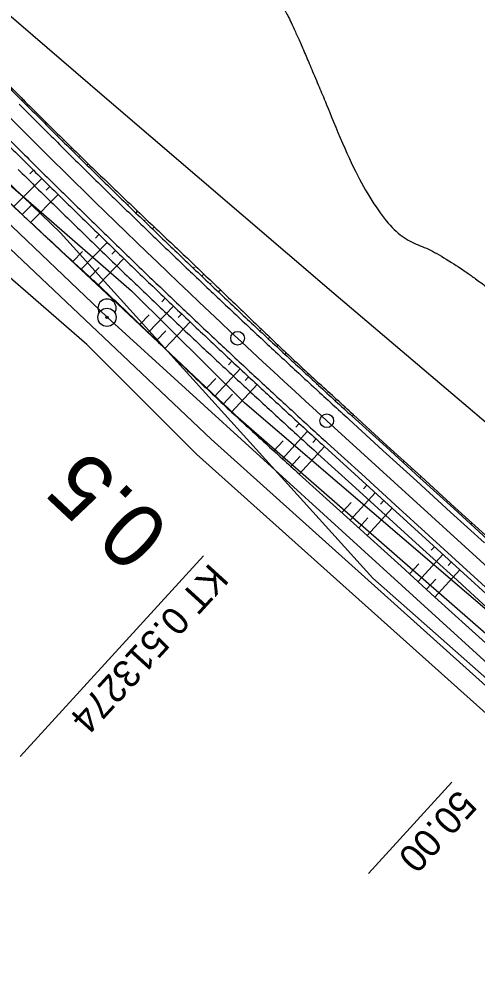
# Model space of a CAD drawing. Extents: x -495905 to -478420, y -1113297 to -1107716.
# Drawn here: x -481388.3 to -481338.3, y -1113006.1 to -1112902.5 of the extents above; entities that cross this region are included whole.
import ezdxf

# ---------------------------------------------------------------- set-up
doc = ezdxf.new("R2010")
doc.units = 0
for name, color, linetype in [('01_OBVOD PÚ', 7, 'Continuous'), ('07_VODOVOD', 7, 'Continuous'), ('2D_VRSTEVNICE', 7, 'Continuous'), ('C11_HATCH_SLOPE_L', 7, 'Continuous'), ('C11_HATCH_SLOPE_R', 7, 'Continuous'), ('C11_HECTOMETRY', 7, 'Continuous'), ('C11_HLBODY', 7, 'Continuous'), ('C11_HRANA_TELESO', 7, 'Continuous'), ('C11_KORUNA', 7, 'Continuous'), ('C11_OSA', 7, 'Continuous'), ('C11_PRIKOP', 7, 'Continuous'), ('C11_STANICENI', 7, 'Continuous'), ('C11_VOZOVKA', 7, 'Continuous'), ('C11_ZPEVKRAJ', 7, 'Continuous'), ('ODVODNĚNÍ PLOŠNÉ', 7, 'Continuous'), ('zamereni', 7, 'Continuous')]:
    doc.layers.add(name, color=color, linetype=linetype)

msp = doc.modelspace()

# ---------------------------------------------------------------- linework, layer by layer
at = {"layer": '01_OBVOD PÚ'}
for p, q in [((-481426.67, -1112889.24), (-481378.69, -1112935.08)), ((-481378.69, -1112935.08), (-481286.24, -1113019.27))]:
    msp.add_line(p, q, dxfattribs=at)
at = {"layer": '07_VODOVOD'}
msp.add_lwpolyline([(-481447.47, -1112865.77), (-481438.82, -1112866.21), (-481429.96, -1112867.07), (-481404.32, -1112889.15), (-481378.96, -1112910.98), (-481353.92, -1112932.45), (-481328.63, -1112953.9), (-481296.87, -1112980.63), (-481265.19, -1113007.37), (-481233.34, -1113034.37), (-481201.77, -1113061.42), (-481169.99, -1113088.44), (-481138.52, -1113115.13), (-481106.63, -1113142.02), (-481094.66, -1113152.18)], dxfattribs=at)
at = {"layer": '2D_VRSTEVNICE'}
msp.add_open_spline([(-481551.3, -1112756.92), (-481547.44, -1112761.88), (-481547.11, -1112762.46), (-481545.92, -1112763.5), (-481537.58, -1112762.56), (-481513.68, -1112779.11), (-481513.68, -1112779.11), (-481513.68, -1112779.11), (-481491.05, -1112801.05), (-481482.63, -1112813.08), (-481477.05, -1112818.52), (-481476.8, -1112818.75), (-481456.22, -1112823.29), (-481442.02, -1112835.86), (-481424.8, -1112850.42), (-481413.21, -1112859.51), (-481391.62, -1112878.03), (-481383.26, -1112885.76), (-481360.32, -1112899.5), (-481357.85, -1112904.16), (-481349.13, -1112925.41), (-481341.11, -1112928.52), (-481329.78, -1112937.87), (-481311.64, -1112957.65), (-481301.83, -1112966.08), (-481283.86, -1112978.01), (-481278.86, -1112980.3), (-481258.37, -1112999.07), (-481255.38, -1113002.96), (-481236.21, -1113021.08), (-481230.44, -1113026.21), (-481206.76, -1113043.85), (-481197.57, -1113052.01), (-481170.89, -1113066.19)], degree=2, dxfattribs=at)
at = {"layer": 'C11_HATCH_SLOPE_L'}
for p, q in [((-481387.96, -1112911.41), (-481387.84, -1112911.3)), ((-481383.54, -1112915.82), (-481383.48, -1112915.75)), ((-481383.42, -1112915.69), (-481383.42, -1112915.69)), ((-481382.66, -1112916.7), (-481382.53, -1112916.56)), ((-481381.77, -1112917.57), (-481381.7, -1112917.5)), ((-481381.63, -1112917.43), (-481381.63, -1112917.43)), ((-481380.88, -1112918.45), (-481380.74, -1112918.3)), ((-481376.43, -1112922.81), (-481376.34, -1112922.72)), ((-481376.25, -1112922.62), (-481376.25, -1112922.62)), ((-481375.53, -1112923.68), (-481375.35, -1112923.49)), ((-481374.64, -1112924.55), (-481374.54, -1112924.45)), ((-481374.44, -1112924.35), (-481374.44, -1112924.35)), ((-481373.74, -1112925.41), (-481373.54, -1112925.21)), ((-481369.24, -1112929.73), (-481369.12, -1112929.61)), ((-481369.01, -1112929.49), (-481369.01, -1112929.49)), ((-481368.34, -1112930.59), (-481368.11, -1112930.35)), ((-481367.43, -1112931.45), (-481367.32, -1112931.33)), ((-481367.21, -1112931.21), (-481367.21, -1112931.21)), ((-481366.53, -1112932.31), (-481366.3, -1112932.07)), ((-481361.98, -1112936.58), (-481361.9, -1112936.49)), ((-481361.81, -1112936.39), (-481361.81, -1112936.39)), ((-481361.07, -1112937.43), (-481360.91, -1112937.26)), ((-481360.16, -1112938.28), (-481360.08, -1112938.2)), ((-481360.01, -1112938.12), (-481360.01, -1112938.12)), ((-481359.24, -1112939.13), (-481359.1, -1112938.98)), ((-481354.66, -1112943.35), (-481354.6, -1112943.28)), ((-481354.53, -1112943.22), (-481354.53, -1112943.22)), ((-481353.74, -1112944.2), (-481353.61, -1112944.06)), ((-481352.82, -1112945.04), (-481352.75, -1112944.97)), ((-481352.69, -1112944.9), (-481352.69, -1112944.9)), ((-481351.89, -1112945.88), (-481351.77, -1112945.74)), ((-481347.28, -1112950.09), (-481347.21, -1112950.02)), ((-481347.15, -1112949.95), (-481347.15, -1112949.95)), ((-481346.35, -1112950.93), (-481346.23, -1112950.79)), ((-481345.43, -1112951.77), (-481345.36, -1112951.71)), ((-481345.3, -1112951.64), (-481345.3, -1112951.64)), ((-481344.5, -1112952.62), (-481344.38, -1112952.48)), ((-481339.89, -1112956.83), (-481339.82, -1112956.76)), ((-481339.76, -1112956.69), (-481339.76, -1112956.69)), ((-481338.96, -1112957.67), (-481338.84, -1112957.53))]:
    msp.add_line(p, q, dxfattribs=at)
at = {"layer": 'C11_HATCH_SLOPE_R'}
for p, q in [((-481386.72, -1112919.01), (-481387.11, -1112919.41)), ((-481385.83, -1112919.89), (-481388.87, -1112922.97)), ((-481384.04, -1112921.65), (-481387.04, -1112924.7)), ((-481384.93, -1112920.77), (-481385.33, -1112921.17)), ((-481386.84, -1112922.7), (-481387.96, -1112923.84)), ((-481378.67, -1112926.91), (-481381.5, -1112929.83)), ((-481379.57, -1112926.04), (-481379.95, -1112926.43)), ((-481381.38, -1112927.9), (-481382.43, -1112928.98)), ((-481377.77, -1112927.78), (-481378.15, -1112928.18)), ((-481376.86, -1112928.65), (-481379.64, -1112931.52)), ((-481379.55, -1112929.62), (-481380.57, -1112930.68)), ((-481372.35, -1112932.99), (-481372.72, -1112933.38)), ((-481371.44, -1112933.85), (-481374.19, -1112936.74)), ((-481374.09, -1112934.82), (-481375.09, -1112935.87)), ((-481370.53, -1112934.71), (-481370.9, -1112935.11)), ((-481369.62, -1112935.57), (-481372.38, -1112938.49)), ((-481372.28, -1112936.56), (-481373.28, -1112937.62)), ((-481365.06, -1112939.87), (-481365.43, -1112940.26)), ((-481364.14, -1112940.72), (-481366.92, -1112943.71)), ((-481366.81, -1112941.75), (-481367.83, -1112942.84)), ((-481362.3, -1112942.43), (-481365.09, -1112945.44)), ((-481363.22, -1112941.57), (-481363.59, -1112941.97)), ((-481364.98, -1112943.47), (-481366.01, -1112944.57)), ((-481356.77, -1112947.52), (-481359.53, -1112950.54)), ((-481357.7, -1112946.67), (-481358.06, -1112947.07)), ((-481359.44, -1112948.58), (-481360.46, -1112949.69)), ((-481355.85, -1112948.36), (-481356.21, -1112948.76)), ((-481354.92, -1112949.2), (-481357.68, -1112952.22)), ((-481357.59, -1112950.27), (-481358.6, -1112951.38)), ((-481350.31, -1112953.42), (-481350.67, -1112953.81)), ((-481349.38, -1112954.26), (-481352.12, -1112957.26)), ((-481352.03, -1112955.31), (-481353.04, -1112956.42)), ((-481348.46, -1112955.1), (-481348.82, -1112955.49)), ((-481347.54, -1112955.94), (-481350.27, -1112958.94)), ((-481350.18, -1112956.99), (-481351.19, -1112958.09)), ((-481342, -1112961), (-481344.71, -1112963.97)), ((-481342.92, -1112960.15), (-481343.27, -1112960.54)), ((-481344.63, -1112962.03), (-481345.64, -1112963.13)), ((-481341.07, -1112961.84), (-481341.42, -1112962.22)), ((-481340.15, -1112962.68), (-481342.86, -1112965.65)), ((-481342.78, -1112963.71), (-481343.78, -1112964.81))]:
    msp.add_line(p, q, dxfattribs=at)
at = {"layer": 'C11_HECTOMETRY'}
msp.add_circle((-481364.43, -1112937.37), 0.75, dxfattribs=at)
at = {"layer": 'C11_HLBODY'}
msp.add_line((-481368.16, -1112961.16), (-481388.18, -1112983.1), dxfattribs=at)
msp.add_circle((-481354.68, -1112946.38), 0.75, dxfattribs=at)
at = {"layer": 'C11_HRANA_TELESO'}
for p, q in [((-481351.77, -1112945.74), (-481348.07, -1112949.11)), ((-481348.07, -1112949.11), (-481344.38, -1112952.48)), ((-481357.68, -1112952.22), (-481353.97, -1112955.58)), ((-481344.38, -1112952.48), (-481340.68, -1112955.85)), ((-481353.97, -1112955.58), (-481350.27, -1112958.94)), ((-481340.68, -1112955.85), (-481336.99, -1112959.22)), ((-481350.27, -1112958.94), (-481346.56, -1112962.29)), ((-481346.56, -1112962.29), (-481342.86, -1112965.65)), ((-481342.86, -1112965.65), (-481339.15, -1112969.01)), ((-481339.15, -1112969.01), (-481335.45, -1112972.37))]:
    msp.add_line(p, q, dxfattribs=at)
for centre, radius, start, end in [((-479258.59, -1110808.22), 2992.76, 224.55002, 224.64563), ((-480681.84, -1112206.5), 997.58, 224.95085, 225.23733), ((-480686.36, -1112202.08), 997.56, 225.6006, 225.88709), ((-480686.39, -1112202.11), 997.52, 225.88699, 226.17348), ((-480697.01, -1112191.86), 1006.58, 226.43672, 226.72327), ((-480686.56, -1112202), 997.48, 226.18489, 226.47138), ((-480699.38, -1112189.79), 1006.46, 226.90239, 227.18897), ((-480687.66, -1112201.01), 997.44, 226.55661, 226.8431), ((-480703, -1112186.65), 1006.32, 227.46194, 227.74856), ((-480679.68, -1112208.61), 997.42, 226.21009, 226.49658), ((-480684.81, -1112203.71), 1006.23, 226.32831, 226.6148), ((-480672.04, -1112215.89), 997.45, 225.89046, 226.17696), ((-480673.73, -1112214.33), 1006.24, 225.74102, 226.02751), ((-480672.18, -1112215.67), 997.51, 226.1914, 226.4779), ((-480674.24, -1112213.77), 1006.29, 226.07011, 226.3566), ((-480677.51, -1112210.59), 997.55, 226.9005, 227.18698), ((-480674.51, -1112213.46), 1006.33, 226.38005, 226.66654), ((-481690.02, -1113312.3), 498.78, 47.3001, 47.8736), ((-480681.85, -1112206.57), 1006.35, 227.23967, 227.52615), ((-481021.06, -1112578.22), 503.17, 227.4401, 228.0118)]:
    msp.add_arc(centre, radius, start, end, dxfattribs=at)
at = {"layer": 'C11_KORUNA'}
for p, q in [((-481351.89, -1112945.88), (-481348.2, -1112949.25)), ((-481354.92, -1112949.2), (-481351.23, -1112952.57)), ((-481348.2, -1112949.25), (-481344.5, -1112952.62)), ((-481351.23, -1112952.57), (-481347.54, -1112955.94)), ((-481344.5, -1112952.62), (-481340.81, -1112955.99)), ((-481347.54, -1112955.94), (-481343.84, -1112959.31)), ((-481340.81, -1112955.99), (-481337.12, -1112959.36)), ((-481343.84, -1112959.31), (-481340.15, -1112962.68)), ((-481340.15, -1112962.68), (-481336.45, -1112966.05))]:
    msp.add_line(p, q, dxfattribs=at)
for centre, radius, start, end in [((-479264.4, -1110801.9), 2993.25, 224.71435, 224.80996), ((-480680.81, -1112207.53), 997.75, 224.8676, 225.15408), ((-480680.81, -1112207.53), 1002.25, 224.8676, 225.15408), ((-480680.81, -1112207.53), 997.75, 225.15408, 225.44056), ((-480680.81, -1112207.53), 1002.25, 225.15408, 225.44056), ((-480680.81, -1112207.53), 997.75, 225.44056, 225.72704), ((-480680.81, -1112207.53), 1002.25, 225.44056, 225.72704), ((-480680.81, -1112207.53), 997.75, 225.72704, 226.01352), ((-480680.81, -1112207.53), 1002.25, 225.72704, 226.01352), ((-480680.81, -1112207.53), 997.75, 226.01352, 226.3), ((-480680.81, -1112207.53), 1002.25, 226.01352, 226.3), ((-480680.81, -1112207.53), 997.75, 226.3, 226.58648), ((-480680.81, -1112207.53), 1002.25, 226.3, 226.58648), ((-480680.81, -1112207.53), 997.75, 226.58648, 226.87296), ((-480680.81, -1112207.53), 1002.25, 226.58648, 226.87296), ((-480680.81, -1112207.53), 997.75, 226.87296, 227.15944), ((-480680.81, -1112207.53), 1002.25, 226.87296, 227.15944), ((-480680.81, -1112207.53), 997.75, 227.15944, 227.44592), ((-480680.81, -1112207.53), 1002.25, 227.15944, 227.44592), ((-481017.17, -1112575.97), 498.88, 227.2854, 227.8588), ((-481018.69, -1112577.63), 501.12, 227.2857, 227.8582)]:
    msp.add_arc(centre, radius, start, end, dxfattribs=at)
at = {"layer": 'C11_OSA'}
msp.add_line((-481354.68, -1112946.38), (-481297.65, -1112998.4), dxfattribs=at)
msp.add_arc((-480680.81, -1112207.53), 1000, 224.72835, 227.63347, dxfattribs=at)
at = {"layer": 'C11_PRIKOP'}
for p, q in [((-481355.64, -1112949.99), (-481351.95, -1112953.36)), ((-481351.95, -1112953.36), (-481348.25, -1112956.72)), ((-481348.25, -1112956.72), (-481344.55, -1112960.09)), ((-481344.55, -1112960.09), (-481340.85, -1112963.45)), ((-481340.85, -1112963.45), (-481337.15, -1112966.82))]:
    msp.add_line(p, q, dxfattribs=at)
for centre, radius, start, end in [((-480681.64, -1112206.71), 1003.37, 225.22065, 225.50713), ((-480681.64, -1112206.72), 1003.36, 225.50696, 225.79344), ((-480681.65, -1112206.72), 1003.35, 225.79361, 226.08009), ((-480681.66, -1112206.72), 1003.35, 226.08009, 226.36657), ((-480681.66, -1112206.73), 1003.34, 226.3664, 226.65288), ((-480681.66, -1112206.73), 1003.34, 226.6527, 226.93918), ((-480681.67, -1112206.73), 1003.33, 226.93971, 227.22619), ((-480681.67, -1112206.74), 1003.33, 227.22584, 227.51232), ((-481019.48, -1112577.63), 501.66, 227.3523, 227.9246)]:
    msp.add_arc(centre, radius, start, end, dxfattribs=at)
at = {"layer": 'C11_STANICENI'}
msp.add_line((-481341.03, -1112985.9), (-481350.12, -1112995.88), dxfattribs=at)
at = {"layer": 'C11_VOZOVKA'}
for p, q in [((-481352.23, -1112946.25), (-481348.54, -1112949.62)), ((-481354.59, -1112948.83), (-481350.89, -1112952.2)), ((-481348.54, -1112949.62), (-481344.84, -1112952.99)), ((-481350.89, -1112952.2), (-481347.2, -1112955.57)), ((-481344.84, -1112952.99), (-481341.15, -1112956.36)), ((-481347.2, -1112955.57), (-481343.51, -1112958.94)), ((-481341.15, -1112956.36), (-481337.45, -1112959.73)), ((-481343.51, -1112958.94), (-481339.81, -1112962.31)), ((-481339.81, -1112962.31), (-481336.12, -1112965.68))]:
    msp.add_line(p, q, dxfattribs=at)
for centre, radius, start, end in [((-480680.81, -1112207.53), 998.25, 224.8676, 225.15408), ((-480680.81, -1112207.53), 1001.75, 224.8676, 225.15408), ((-480680.81, -1112207.53), 998.25, 225.15408, 225.44056), ((-480680.81, -1112207.53), 1001.75, 225.15408, 225.44056), ((-480680.81, -1112207.53), 998.25, 225.44056, 225.72704), ((-480680.81, -1112207.53), 1001.75, 225.44056, 225.72704), ((-480680.81, -1112207.53), 998.25, 225.72704, 226.01352), ((-480680.81, -1112207.53), 1001.75, 225.72704, 226.01352), ((-480680.81, -1112207.53), 998.25, 226.01352, 226.3), ((-480680.81, -1112207.53), 1001.75, 226.01352, 226.3), ((-480680.81, -1112207.53), 998.25, 226.3, 226.58648), ((-480680.81, -1112207.53), 1001.75, 226.3, 226.58648), ((-480680.81, -1112207.53), 998.25, 226.58648, 226.87296), ((-480680.81, -1112207.53), 1001.75, 226.58648, 226.87296), ((-480680.81, -1112207.53), 998.25, 226.87296, 227.15944), ((-480680.81, -1112207.53), 1001.75, 226.87296, 227.15944), ((-480680.81, -1112207.53), 998.25, 227.15944, 227.44592), ((-480680.81, -1112207.53), 1001.75, 227.15944, 227.44592), ((-481017.34, -1112576.15), 499.12, 227.2854, 227.8587), ((-481018.52, -1112577.44), 500.88, 227.2857, 227.8583)]:
    msp.add_arc(centre, radius, start, end, dxfattribs=at)
at = {"layer": 'C11_ZPEVKRAJ'}
for p, q in [((-481352.23, -1112946.25), (-481348.54, -1112949.62)), ((-481354.59, -1112948.83), (-481350.89, -1112952.2)), ((-481348.54, -1112949.62), (-481344.84, -1112952.99)), ((-481350.89, -1112952.2), (-481347.2, -1112955.57)), ((-481344.84, -1112952.99), (-481341.15, -1112956.36)), ((-481347.2, -1112955.57), (-481343.51, -1112958.94)), ((-481341.15, -1112956.36), (-481337.45, -1112959.73)), ((-481343.51, -1112958.94), (-481339.81, -1112962.31)), ((-481339.81, -1112962.31), (-481336.12, -1112965.68))]:
    msp.add_line(p, q, dxfattribs=at)
for centre, radius, start, end in [((-480680.81, -1112207.53), 998.25, 224.8676, 225.15408), ((-480680.81, -1112207.53), 1001.75, 224.8676, 225.15408), ((-480680.81, -1112207.53), 998.25, 225.15408, 225.44056), ((-480680.81, -1112207.53), 1001.75, 225.15408, 225.44056), ((-480680.81, -1112207.53), 998.25, 225.44056, 225.72704), ((-480680.81, -1112207.53), 1001.75, 225.44056, 225.72704), ((-480680.81, -1112207.53), 998.25, 225.72704, 226.01352), ((-480680.81, -1112207.53), 1001.75, 225.72704, 226.01352), ((-480680.81, -1112207.53), 998.25, 226.01352, 226.3), ((-480680.81, -1112207.53), 1001.75, 226.01352, 226.3), ((-480680.81, -1112207.53), 998.25, 226.3, 226.58648), ((-480680.81, -1112207.53), 1001.75, 226.3, 226.58648), ((-480680.81, -1112207.53), 998.25, 226.58648, 226.87296), ((-480680.81, -1112207.53), 1001.75, 226.58648, 226.87296), ((-480680.81, -1112207.53), 998.25, 226.87296, 227.15944), ((-480680.81, -1112207.53), 1001.75, 226.87296, 227.15944), ((-480680.81, -1112207.53), 998.25, 227.15944, 227.44592), ((-480680.81, -1112207.53), 1001.75, 227.15944, 227.44592), ((-481017.34, -1112576.15), 499.12, 227.2854, 227.8587), ((-481018.52, -1112577.44), 500.88, 227.2857, 227.8583)]:
    msp.add_arc(centre, radius, start, end, dxfattribs=at)
at = {"layer": 'ODVODNĚNÍ PLOŠNÉ'}
msp.add_lwpolyline([(-481426.16, -1112884.94), (-481383.76, -1112925.83), (-481349.63, -1112963.6), (-481309.8, -1112998.79), (-481273.87, -1113029.5), (-481233.31, -1113065.48), (-481187.99, -1113103.18), (-481112.71, -1113161.68), (-481093.99, -1113137.73), (-481062.38, -1113109.2), (-481034.56, -1113086.63), (-481009.15, -1113073.9), (-480966.25, -1113062.37), (-481002.17, -1113037.77), (-481044.22, -1113007.58), (-481079.03, -1112980.74), (-481118.73, -1112955.48), (-481144.71, -1112930.52), (-481180.63, -1112905.92), (-481223.18, -1112868.84)], dxfattribs=at)
at = {"layer": 'zamereni'}
for p, q in [((-481393.33, -1112917.11), (-481376, -1112932.2)), ((-481377.57, -1112933.56), (-481394.22, -1112918.04)), ((-481396.7, -1112920.61), (-481379.74, -1112936.62)), ((-481380.91, -1112938.06), (-481398.74, -1112922.54)), ((-481363.63, -1112944.47), (-481376, -1112932.2)), ((-481377.57, -1112933.56), (-481364.64, -1112945.79)), ((-481367.32, -1112948.39), (-481379.74, -1112936.62)), ((-481380.91, -1112938.06), (-481368.91, -1112950.03)), ((-481329.63, -1112973.58), (-481363.63, -1112944.47)), ((-481364.64, -1112945.79), (-481331.08, -1112975.08)), ((-481334.07, -1112978.28), (-481367.32, -1112948.39)), ((-481368.91, -1112950.03), (-481335.55, -1112979.92))]:
    msp.add_line(p, q, dxfattribs=at)
msp.add_ellipse((-481378.69, -1112934.08), major_axis=(0, -1), ratio=0.999955, start_param=1.047987, end_param=5.236518, dxfattribs=at)
for major_axis in [(0, -1), (0, -0.133)]:
    msp.add_ellipse((-481378.69, -1112935.08), major_axis=major_axis, ratio=0.999955, dxfattribs=at)

# ---------------------------------------------------------------- texts
at = {"layer": 'C11_HECTOMETRY'}
msp.add_text('0.5', height=7, rotation=136.8273, dxfattribs=at).set_placement((-481371.51, -1112958.16))
at = {"layer": 'C11_HLBODY'}
msp.add_text('KT 0.513274', height=2.999, rotation=227.6335, dxfattribs=at).set_placement((-481367.42, -1112961.83))
at = {"layer": 'C11_STANICENI'}
msp.add_text('50.00', height=3, rotation=227.6335, dxfattribs=at).set_placement((-481340.29, -1112986.58))

doc.saveas('drawing.dxf')
